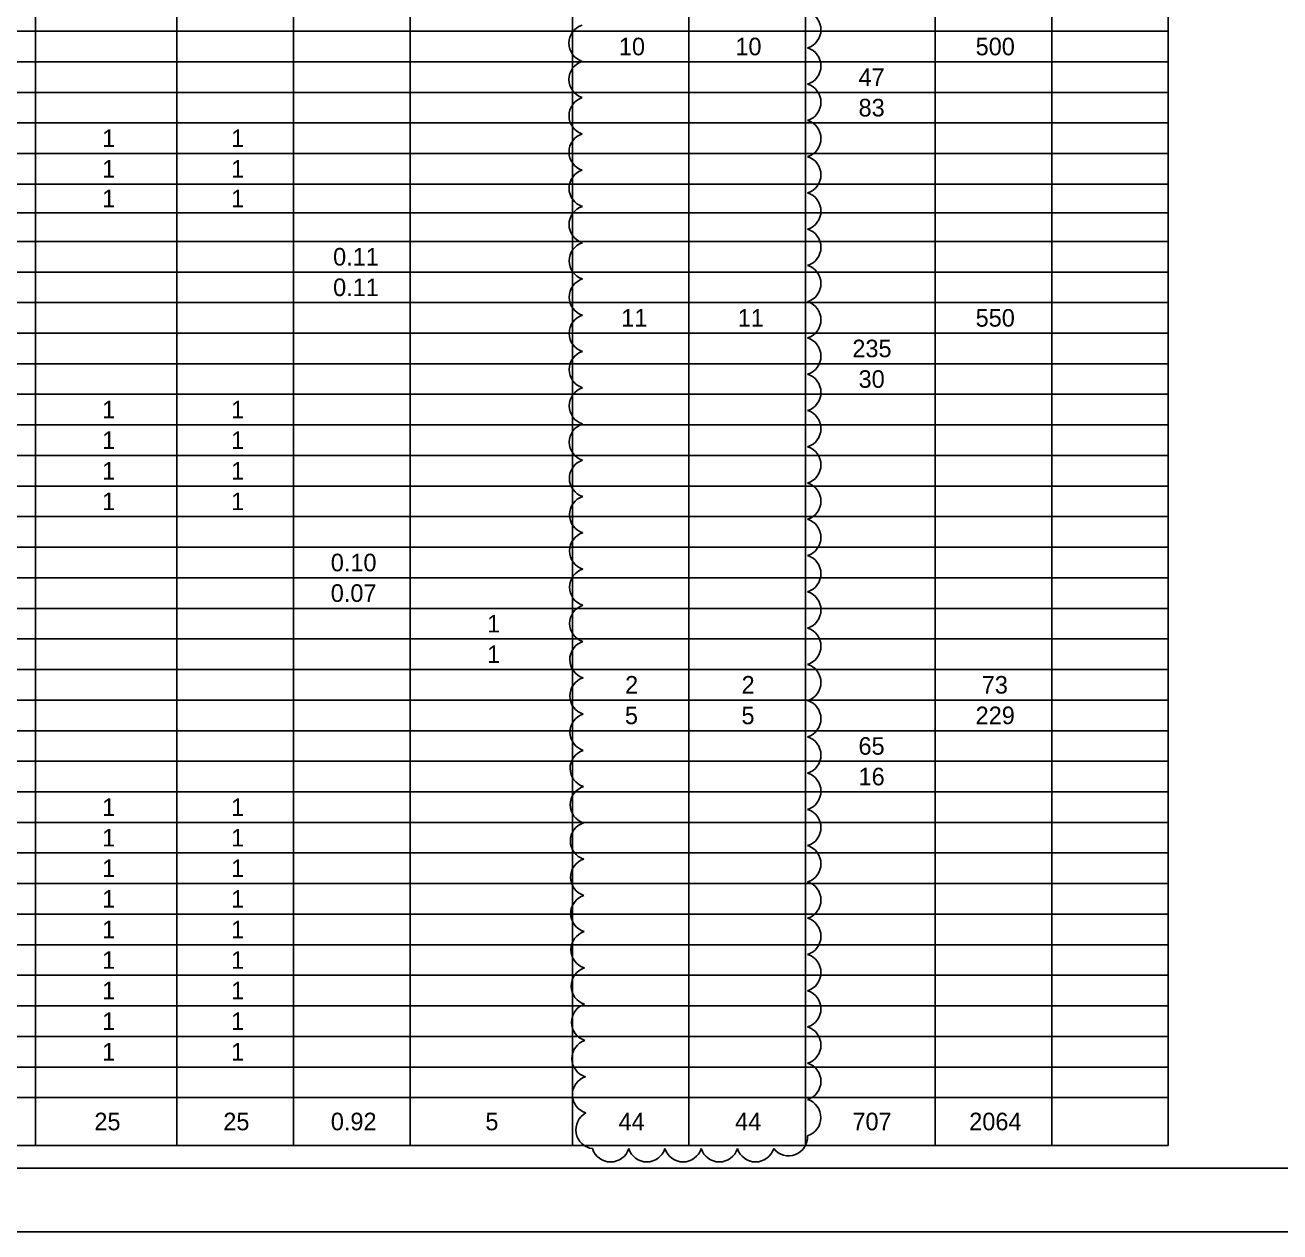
# Model space of a CAD drawing. Extents: x 0 to 36.6, y 0 to 22.
# Drawn here: x 16.89 to 26.75, y 0 to 9.47 of the extents above; entities that cross this region are included whole.
import ezdxf

# ---------------------------------------------------------------- set-up
doc = ezdxf.new("R2010")
doc.units = 0
for name, color, linetype in [('SC_Scratch2', 7, 'Continuous'), ('SH_Border', 7, 'Continuous'), ('SH_Cut_Line', 7, 'Continuous'), ('SH_Text', 7, 'Continuous')]:
    doc.layers.add(name, color=color, linetype=linetype)

msp = doc.modelspace()

# ---------------------------------------------------------------- linework, layer by layer
at = {"layer": 'SC_Scratch2'}
for centre, radius, start, end in [((22.9928, 9.4355), 0.1492, 287.5, 72.5), ((21.3125, 9.3296), 0.1492, 107.52053, 252.52053), ((22.9928, 9.1509), 0.1492, 287.5, 72.5), ((21.3126, 9.045), 0.1492, 107.52487, 252.52487), ((22.9928, 8.8663), 0.1492, 287.5, 72.5), ((21.3127, 8.7604), 0.1492, 107.52943, 252.52943), ((22.9928, 8.5817), 0.1492, 287.5, 72.5), ((21.3129, 8.4758), 0.1492, 107.53424, 252.53424), ((22.9928, 8.297), 0.1492, 287.5, 72.5), ((21.3131, 8.1912), 0.1492, 107.53932, 252.53932), ((22.9928, 8.0124), 0.1492, 287.5, 72.5), ((21.3133, 7.9066), 0.1492, 107.5447, 252.5447), ((22.9928, 7.7278), 0.1492, 287.5, 72.5), ((21.3135, 7.6219), 0.1492, 107.5504, 252.5504), ((22.9928, 7.4432), 0.1492, 287.5, 72.5), ((21.3138, 7.3373), 0.1492, 107.55646, 252.55646), ((22.9928, 7.1586), 0.1492, 287.5, 72.5), ((21.3141, 7.0527), 0.1492, 107.56292, 252.56292), ((22.9928, 6.874), 0.1492, 287.5, 72.5), ((21.3144, 6.7681), 0.1492, 107.56983, 252.56983), ((22.9928, 6.5893), 0.1492, 287.5, 72.5), ((21.3148, 6.4835), 0.1492, 107.57724, 252.57724), ((22.9928, 6.3047), 0.1492, 287.5, 72.5), ((21.3152, 6.1989), 0.1492, 107.58522, 252.58522), ((22.9928, 6.0201), 0.1492, 287.5, 72.5), ((21.3156, 5.9143), 0.1492, 107.59383, 252.59383), ((22.9928, 5.7355), 0.1492, 287.5, 72.5), ((21.3161, 5.6297), 0.1492, 107.60317, 252.60317), ((22.9928, 5.4509), 0.1492, 287.5, 72.5), ((21.3166, 5.345), 0.1492, 107.61335, 252.61335), ((22.9928, 5.1663), 0.1492, 287.5, 72.5), ((21.3172, 5.0604), 0.1492, 107.6245, 252.6245), ((22.9928, 4.8816), 0.1492, 287.5, 72.5), ((21.3179, 4.7758), 0.1492, 107.63679, 252.63679), ((22.9928, 4.597), 0.1492, 287.5, 72.5), ((21.3186, 4.4912), 0.1492, 107.65043, 252.65043), ((22.9928, 4.3124), 0.1492, 287.5, 72.5), ((21.3194, 4.2066), 0.1492, 107.66567, 252.66567), ((22.9928, 4.0278), 0.1492, 287.5, 72.5), ((21.3202, 3.922), 0.1492, 107.68286, 252.68286), ((22.9928, 3.7432), 0.1492, 287.5, 72.5), ((21.3212, 3.6374), 0.1492, 107.70246, 252.70246), ((22.9928, 3.4585), 0.1492, 287.5, 72.5), ((21.3223, 3.3528), 0.1492, 107.7251, 252.7251), ((22.9928, 3.1739), 0.1492, 287.5, 72.5), ((21.3234, 3.0682), 0.1492, 107.75163, 252.75163), ((22.9928, 2.8893), 0.1492, 287.5, 72.5), ((21.3248, 2.7836), 0.1492, 107.78334, 252.78334), ((22.9928, 2.6047), 0.1492, 287.5, 72.5), ((21.3263, 2.4991), 0.1492, 107.82215, 252.82215), ((22.9928, 2.3201), 0.1492, 287.5, 72.5), ((21.328, 2.2145), 0.1492, 107.87121, 252.87121), ((22.9928, 2.0355), 0.1492, 287.5, 72.5), ((21.33, 1.9299), 0.1492, 107.93599, 252.93599), ((22.9928, 1.7508), 0.1492, 287.5, 72.5), ((21.3324, 1.6454), 0.1492, 108.02732, 253.02732), ((22.9928, 1.4662), 0.1492, 287.5, 72.5), ((21.3354, 1.3609), 0.1492, 108.17053, 253.17053), ((22.9928, 1.1816), 0.1492, 287.5, 72.5), ((21.3394, 1.0765), 0.1492, 108.4486, 253.4486), ((22.9923, 0.897), 0.1493, 287.32041, 72.32041), ((21.3666, 0.8015), 0.1493, 117.84542, 262.84542), ((22.888, 0.7458), 0.1491, 218.31906, 3.31906), ((21.4903, 0.6982), 0.1492, 197.5, 342.5), ((21.7748, 0.6983), 0.1492, 197.5, 342.5), ((22.0595, 0.6983), 0.1492, 197.5, 342.5), ((22.3441, 0.6983), 0.1492, 197.5, 342.5), ((22.6287, 0.6983), 0.1492, 197.5, 342.5)]:
    msp.add_arc(centre, radius, start, end, dxfattribs=at)
at = {"layer": 'SH_Border'}
msp.add_lwpolyline([(1.5, 21.5), (33.5, 21.5), (33.5, 0.5), (1.5, 0.5)], close=True, dxfattribs=at)
at = {"layer": 'SH_Cut_Line'}
msp.add_lwpolyline([(0, 0), (34, 0), (34, 22), (0, 22)], close=True, dxfattribs=at)
at = {"layer": 'SH_Text'}
for p, q in [((16.9749, 21.304), (16.9749, 0.679)), ((23.0199, 21.304), (23.0199, 0.679)), ((24.0399, 21.304), (24.0399, 0.679)), ((24.9549, 21.304), (24.9549, 0.679)), ((25.8699, 21.304), (25.8699, 0.679)), ((18.0849, 20.944), (18.0849, 0.679)), ((18.9999, 20.944), (18.9999, 0.679)), ((19.9149, 20.944), (19.9149, 0.679)), ((21.1899, 20.944), (21.1899, 0.679)), ((22.1049, 20.944), (22.1049, 0.679)), ((9.1449, 9.424), (25.8699, 9.424)), ((9.1449, 9.184), (25.8699, 9.184)), ((9.1449, 8.944), (25.8699, 8.944)), ((9.1449, 8.704), (25.8699, 8.704)), ((9.1449, 8.464), (25.8699, 8.464)), ((9.1449, 8.224), (25.8699, 8.224)), ((9.1449, 7.999), (25.8699, 7.999)), ((9.1449, 7.774), (25.8699, 7.774)), ((9.1449, 7.534), (25.8699, 7.534)), ((9.1449, 7.294), (25.8699, 7.294)), ((9.1449, 7.054), (25.8699, 7.054)), ((9.1449, 6.814), (25.8699, 6.814)), ((9.1449, 6.574), (25.8699, 6.574)), ((9.1449, 6.334), (25.8699, 6.334)), ((9.1449, 6.094), (25.8699, 6.094)), ((9.1449, 5.854), (25.8699, 5.854)), ((9.1449, 5.614), (25.8699, 5.614)), ((9.1449, 5.374), (25.8699, 5.374)), ((9.1449, 5.134), (25.8699, 5.134)), ((9.1449, 4.894), (25.8699, 4.894)), ((9.1449, 4.654), (25.8699, 4.654)), ((9.1449, 4.414), (25.8699, 4.414)), ((9.1449, 4.174), (25.8699, 4.174)), ((9.1449, 3.934), (25.8699, 3.934)), ((9.1449, 3.694), (25.8699, 3.694)), ((9.1449, 3.454), (25.8699, 3.454)), ((9.1449, 3.214), (25.8699, 3.214)), ((9.1449, 2.974), (25.8699, 2.974)), ((9.1449, 2.734), (25.8699, 2.734)), ((9.1449, 2.494), (25.8699, 2.494)), ((9.1449, 2.254), (25.8699, 2.254)), ((9.1449, 2.014), (25.8699, 2.014)), ((9.1449, 1.774), (25.8699, 1.774)), ((9.1449, 1.534), (25.8699, 1.534)), ((9.1449, 1.294), (25.8699, 1.294)), ((9.1449, 1.054), (25.8699, 1.054)), ((9.1449, 0.679), (25.8699, 0.679))]:
    msp.add_line(p, q, dxfattribs=at)

# ---------------------------------------------------------------- texts
for s, p in [('10', (21.5551, 9.235)), ('10', (22.4701, 9.235)), ('500', (24.3569, 9.235)), ('47', (23.4374, 8.995)), ('83', (23.4374, 8.755)), ('1', (17.4977, 8.515)), ('1', (18.5102, 8.515)), ('1', (17.4977, 8.275)), ('1', (18.5102, 8.275)), ('1', (17.4977, 8.0425)), ('1', (18.5102, 8.0425)), ('0.11', (19.311, 7.585)), ('0.11', (19.311, 7.345)), ('11', (21.5734, 7.105)), ('11', (22.4884, 7.105)), ('550', (24.3569, 7.105)), ('235', (23.3887, 6.865)), ('30', (23.4376, 6.625)), ('1', (17.4977, 6.385)), ('1', (18.5102, 6.385)), ('1', (17.4977, 6.145)), ('1', (18.5102, 6.145)), ('1', (17.4977, 5.905)), ('1', (18.5102, 5.905)), ('1', (17.4977, 5.665)), ('1', (18.5102, 5.665)), ('0.10', (19.2928, 5.185)), ('0.07', (19.2926, 4.945)), ('1', (20.5202, 4.705)), ('1', (20.5202, 4.465)), ('2', (21.6038, 4.225)), ('2', (22.5188, 4.225)), ('73', (24.4049, 4.225)), ('5', (21.6027, 3.985)), ('5', (22.5177, 3.985)), ('229', (24.3566, 3.985)), ('65', (23.4369, 3.745)), ('16', (23.4374, 3.505)), ('1', (17.4977, 3.265)), ('1', (18.5102, 3.265)), ('1', (17.4977, 3.025)), ('1', (18.5102, 3.025)), ('1', (17.4977, 2.785)), ('1', (18.5102, 2.785)), ('1', (17.4977, 2.545)), ('1', (18.5102, 2.545)), ('1', (17.4977, 2.305)), ('1', (18.5102, 2.305)), ('1', (17.4977, 2.065)), ('1', (18.5102, 2.065)), ('1', (17.4977, 1.825)), ('1', (18.5102, 1.825)), ('1', (17.4977, 1.585)), ('1', (18.5102, 1.585)), ('1', (17.4977, 1.345)), ('1', (18.5102, 1.345)), ('25', (17.4361, 0.7975)), ('25', (18.4486, 0.7975)), ('0.92', (19.293, 0.7975)), ('5', (20.5068, 0.7975)), ('44', (21.553, 0.7975)), ('44', (22.468, 0.7975)), ('707', (23.3891, 0.7975)), ('2064', (24.3065, 0.7975))]:
    msp.add_text(s, height=0.138, dxfattribs=at).set_placement(p)

doc.saveas('drawing.dxf')
